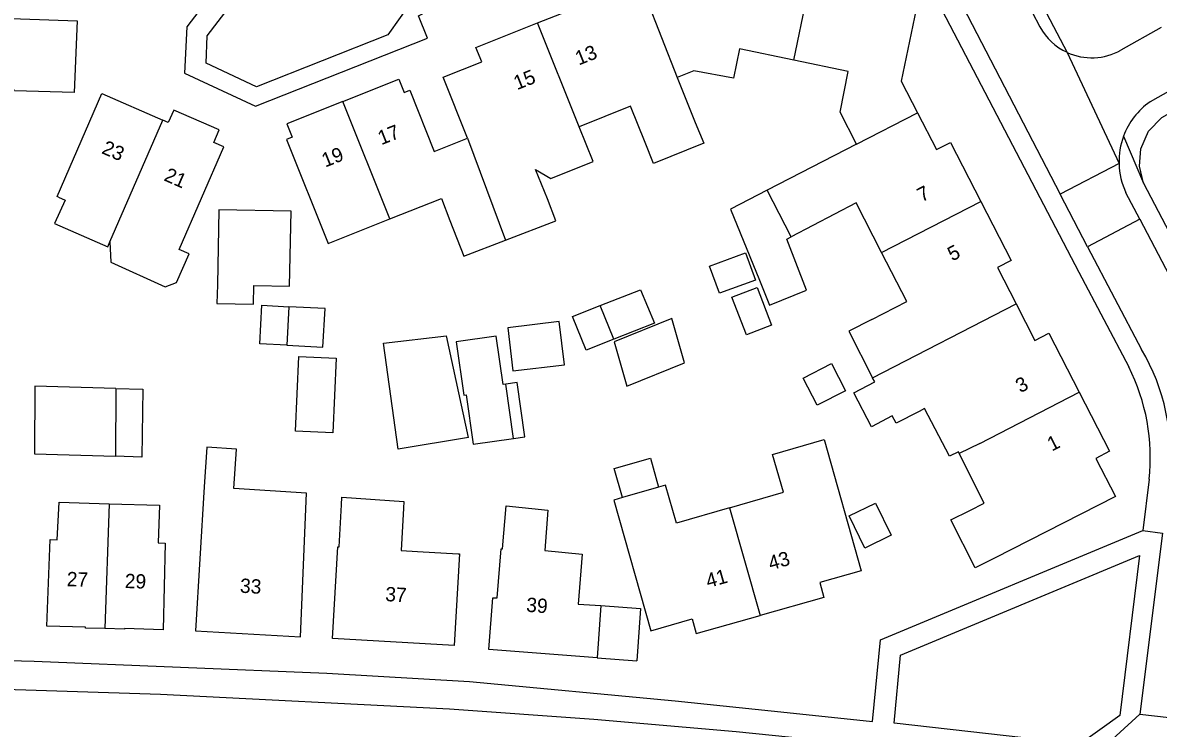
# Model space of a CAD drawing. Extents: x 194485 to 197793, y 468269 to 470822.
# Drawn here: x 195092.1 to 195187.3, y 470211.6 to 470270.8 of the extents above; entities that cross this region are included whole.
import ezdxf

# ---------------------------------------------------------------- set-up
doc = ezdxf.new("R2010")
doc.units = 0
for name, color, linetype in [('BGT grensvlak gebouwinstallatie plus 1', 7, 'Continuous'), ('BGT grensvlak overig bouwwerk uitbreiding populatie', 7, 'Continuous'), ('BGT grensvlak pand op maaiveld', 7, 'Continuous'), ('BGT grensvlak pand op maaiveld LR', 7, 'Continuous'), ('BGT grensvlak wegdeel', 7, 'Continuous'), ('BGT tekst huisnummerreeks', 7, 'Continuous')]:
    doc.layers.add(name, color=color, linetype=linetype)

msp = doc.modelspace()

# ---------------------------------------------------------------- linework, layer by layer
at = {"layer": 'BGT grensvlak gebouwinstallatie plus 1'}
for p, q in [((195154.51, 470256.704), (195151.434, 470255.12)), ((195151.434, 470255.12), (195153.855, 470249.162)), ((195156.152, 470252.615), (195156.515, 470252.803)), ((195157.792, 470248.326), (195156.152, 470252.615)), ((195153.855, 470249.162), (195154.704, 470247.072)), ((195154.704, 470247.072), (195157.792, 470248.326)), ((195117.456, 470246.783), (195114.433, 470246.946)), ((195117.282, 470243.545), (195117.456, 470246.783)), ((195114.259, 470243.707), (195117.282, 470243.545)), ((195141.683, 470233.384), (195144.719, 470234.234)), ((195144.719, 470234.234), (195145.4, 470231.804)), ((195142.37, 470230.933), (195141.683, 470233.384)), ((195140.568, 470221.876), (195143.88, 470221.651)), ((195143.88, 470221.651), (195143.575, 470217.238)), ((195140.266, 470217.496), (195143.575, 470217.238))]:
    msp.add_line(p, q, dxfattribs=at)
for points in [[(195141.652, 470244.219), (195139.344, 470243.289), (195138.201, 470246.125), (195140.509, 470247.055)], [(195133.204, 470241.559), (195137.518, 470242.078), (195137.082, 470245.703), (195132.768, 470245.184), (195133.204, 470241.559)], [(195146.524, 470245.946), (195141.674, 470244.006), (195142.735, 470240.288), (195147.585, 470242.229), (195146.524, 470245.946)], [(195133.258, 470235.894), (195134.192, 470236.026), (195133.548, 470240.577), (195132.614, 470240.444)]]:
    msp.add_lwpolyline(points, dxfattribs=at)
at = {"layer": 'BGT grensvlak overig bouwwerk uitbreiding populatie'}
for p, q in [((195149.68, 470250.358), (195152.685, 470251.45)), ((195152.685, 470251.45), (195153.517, 470249.161)), ((195150.512, 470248.069), (195149.68, 470250.358)), ((195153.517, 470249.161), (195150.512, 470248.069)), ((195151.553, 470247.75), (195153.667, 470248.557)), ((195153.667, 470248.557), (195154.873, 470245.398)), ((195152.76, 470244.591), (195151.553, 470247.75)), ((195111.992, 470243.829), (195112.166, 470247.067)), ((195112.166, 470247.067), (195114.433, 470246.946)), ((195114.433, 470246.946), (195114.259, 470243.707)), ((195154.873, 470245.398), (195152.76, 470244.591)), ((195114.259, 470243.707), (195111.992, 470243.829)), ((195157.526, 470240.964), (195159.9, 470242.172)), ((195159.9, 470242.172), (195161.06, 470239.893)), ((195158.686, 470238.684), (195157.526, 470240.964)), ((195161.06, 470239.893), (195158.686, 470238.684))]:
    msp.add_line(p, q, dxfattribs=at)
at = {"layer": 'BGT grensvlak pand op maaiveld'}
for p, q in [((195146.957, 470266.177), (195148.48, 470262.391)), ((195104.32, 470262.388), (195103.88, 470262.58)), ((195104.776, 470263.433), (195104.32, 470262.388)), ((195108.59, 470261.767), (195104.776, 470263.433)), ((195108.133, 470260.723), (195108.59, 470261.767)), ((195162, 470260.562), (195154.51, 470256.704)), ((195136.09, 470256.004), (195135.104, 470258.458)), ((195156.515, 470252.803), (195154.51, 470256.704)), ((195161.964, 470255.643), (195156.515, 470252.803)), ((195164.098, 470251.491), (195161.964, 470255.643)), ((195140.509, 470247.055), (195143.889, 470248.369)), ((195141.652, 470244.219), (195140.509, 470247.055)), ((195129.49, 470235.969), (195127.624, 470244.509)), ((195163.519, 470240.646), (195163.345, 470240.985)), ((195133.258, 470235.894), (195132.614, 470240.444)), ((195167.702, 470238.402), (195167.236, 470238.162)), ((195172.679, 470230.467), (195170.607, 470234.623)), ((195145.4, 470231.804), (195142.37, 470230.933)), ((195171.501, 470229.862), (195172.679, 470230.467)), ((195124.029, 470230.042), (195123.84, 470226.509)), ((195123.84, 470226.509), (195125.201, 470226.429)), ((195125.201, 470226.429), (195128.625, 470226.228)), ((195140.568, 470221.876), (195140.266, 470217.496))]:
    msp.add_line(p, q, dxfattribs=at)
for points in [[(195158.616, 470276.679), (195164.068, 470275.544), (195163.462, 470272.606), (195166.993, 470271.905), (195165.741, 470265.864), (195167.115, 470263.198)], [(195135.26, 470270.736), (195140.419, 470272.798), (195140.901, 470271.591), (195144.326, 470272.951)], [(195096.449, 470264.899), (195091.441, 470265.047), (195087.958, 470271.234), (195096.684, 470270.927), (195096.449, 470264.899)], [(195129.392, 470261.087), (195127.348, 470266.193), (195130.585, 470267.467), (195130.101, 470268.673), (195135.26, 470270.736)], [(195156.73, 470267.621), (195152.188, 470268.566), (195151.678, 470266.118), (195148.355, 470266.72), (195146.957, 470266.177)], [(195162, 470260.562), (195160.622, 470263.245), (195161.302, 470266.669), (195156.73, 470267.621)], [(195118.954, 470264.149), (195123.655, 470266.021), (195124.098, 470264.906), (195124.563, 470265.091)], [(195095.136, 470256.119), (195095.013, 470256.173), (195098.769, 470264.811), (195103.88, 470262.58)], [(195124.563, 470265.091), (195126.596, 470259.972), (195129.392, 470261.087)], [(195118.954, 470264.149), (195114.253, 470262.277), (195114.697, 470261.162), (195114.232, 470260.977)], [(195144.295, 470260.708), (195143.067, 470263.76), (195138.744, 470262.02)], [(195167.115, 470263.198), (195168.701, 470260.119), (195169.856, 470260.714), (195172.403, 470255.77)], [(195135.104, 470258.458), (195136.392, 470257.69), (195139.914, 470259.108), (195138.744, 470262.02)], [(195148.48, 470262.391), (195149.2, 470260.65), (195144.971, 470258.952), (195144.295, 470260.708)], [(195105.227, 470251.75), (195108.991, 470260.348), (195108.133, 470260.723)], [(195114.232, 470260.977), (195117.71, 470252.244), (195122.875, 470254.303)], [(195095.136, 470256.119), (195095.675, 470255.885), (195094.793, 470253.909)], [(195122.875, 470254.303), (195127.213, 470256.032), (195127.929, 470254.174)], [(195132.576, 470252.524), (195136.79, 470254.158), (195136.09, 470256.004)], [(195111.503, 470248.725), (195114.49, 470248.671), (195114.625, 470254.96), (195108.566, 470255.08), (195108.448, 470248.781)], [(195172.403, 470255.77), (195174.95, 470250.827), (195173.794, 470250.232), (195175.368, 470247.177)], [(195127.929, 470254.174), (195129.086, 470251.171), (195132.576, 470252.524)], [(195094.793, 470253.909), (195099.249, 470251.973), (195099.427, 470252.38)], [(195099.427, 470252.38), (195099.504, 470250.689), (195104.053, 470248.624), (195105.022, 470248.972), (195106.066, 470251.385), (195105.227, 470251.75)], [(195163.273, 470245.876), (195166.208, 470247.384), (195164.098, 470251.491)], [(195108.448, 470248.781), (195108.402, 470247.211), (195111.466, 470247.164), (195111.503, 470248.725)], [(195143.889, 470248.369), (195145.055, 470245.555), (195141.652, 470244.219)], [(195175.368, 470247.177), (195176.941, 470244.122), (195178.097, 470244.717), (195180.645, 470239.77)], [(195163.273, 470245.876), (195161.342, 470244.884), (195163.345, 470240.985)], [(195129.49, 470235.969), (195123.597, 470234.996), (195122.366, 470243.875), (195127.624, 470244.509)], [(195132.614, 470240.444), (195132.373, 470240.41), (195131.799, 470244.47), (195128.453, 470243.996), (195129.087, 470239.519), (195129.285, 470239.547), (195129.87, 470235.414), (195133.258, 470235.894)], [(195118.402, 470242.634), (195118.107, 470236.365), (195114.972, 470236.513), (195115.268, 470242.782), (195118.402, 470242.634)], [(195164.989, 470237.785), (195163.256, 470236.877), (195161.764, 470239.726), (195163.519, 470240.646)], [(195099.922, 470240.095), (195093.132, 470240.295), (195093.121, 470234.619), (195099.904, 470234.404)], [(195099.922, 470240.095), (195102.201, 470240.028), (195102.113, 470234.334), (195099.904, 470234.404)], [(195180.645, 470239.77), (195183.193, 470234.824), (195182.039, 470234.23), (195183.688, 470231.028), (195173.562, 470225.85)], [(195167.236, 470238.162), (195165.305, 470237.169), (195164.989, 470237.785)], [(195170.607, 470234.623), (195170.534, 470234.771), (195169.776, 470234.413), (195167.702, 470238.402)], [(195109.824, 470231.687), (195110.047, 470235.001), (195107.546, 470235.159), (195107.322, 470231.845)], [(195151.347, 470230.082), (195155.871, 470231.384), (195154.959, 470234.555), (195159.284, 470235.799), (195162.37, 470224.802), (195158.905, 470223.816), (195159.26, 470222.566), (195153.912, 470221.047)], [(195107.322, 470231.845), (195106.607, 470219.775), (195115.4, 470219.266), (195115.899, 470231.305), (195109.824, 470231.687)], [(195151.347, 470230.082), (195146.905, 470228.804), (195145.993, 470231.975), (195145.4, 470231.804)], [(195099.013, 470219.948), (195097.395, 470220), (195097.397, 470220.06), (195094.149, 470220.165), (195094.414, 470227.424), (195095.018, 470227.405), (195095.176, 470230.557), (195099.384, 470230.425)], [(195099.384, 470230.425), (195103.591, 470230.292), (195103.47, 470227.142), (195104.065, 470227.124), (195103.883, 470219.85), (195100.645, 470219.955), (195100.643, 470219.895), (195099.013, 470219.948)], [(195128.625, 470226.228), (195128.728, 470226.222), (195128.283, 470218.525), (195118.075, 470219.113), (195118.538, 470226.82), (195118.642, 470226.814), (195118.848, 470230.329)], [(195118.848, 470230.329), (195118.879, 470230.986), (195124.069, 470230.623), (195124.029, 470230.042)], [(195140.266, 470217.496), (195131.187, 470218.203), (195131.528, 470222.544), (195131.872, 470222.546), (195132.228, 470226.633), (195132.33, 470226.634), (195132.637, 470230.25), (195136.132, 470229.89)], [(195142.37, 470230.933), (195141.668, 470230.731), (195144.758, 470219.779), (195148.21, 470220.78), (195148.565, 470219.529), (195153.912, 470221.047)], [(195161.375, 470229.404), (195163.578, 470230.476), (195164.9, 470227.797), (195162.682, 470226.711), (195161.375, 470229.404)], [(195136.132, 470229.89), (195135.874, 470226.504), (195139.011, 470226.193), (195138.681, 470222.004), (195140.568, 470221.876)], [(195173.562, 470225.85), (195171.945, 470225.059), (195169.885, 470229.078), (195171.501, 470229.862)]]:
    msp.add_lwpolyline(points, dxfattribs=at)
at = {"layer": 'BGT grensvlak pand op maaiveld LR'}
for p, q in [((195156.73, 470267.621), (195158.616, 470276.679)), ((195144.326, 470272.951), (195146.957, 470266.177)), ((195138.744, 470262.02), (195135.26, 470270.736)), ((195122.875, 470254.303), (195118.954, 470264.149)), ((195099.427, 470252.38), (195103.88, 470262.58)), ((195162, 470260.562), (195167.115, 470263.198)), ((195129.392, 470261.087), (195132.576, 470252.524)), ((195164.098, 470251.491), (195172.403, 470255.77)), ((195163.345, 470240.985), (195175.368, 470247.177)), ((195099.922, 470240.095), (195099.904, 470234.404)), ((195172.322, 470235.484), (195180.645, 470239.77)), ((195172.322, 470235.484), (195170.607, 470234.623)), ((195099.384, 470230.425), (195099.013, 470219.948)), ((195151.347, 470230.082), (195153.912, 470221.047))]:
    msp.add_line(p, q, dxfattribs=at)
at = {"layer": 'BGT grensvlak wegdeel'}
for p, q in [((195257.786, 470304.19), (195186.59, 470264.129)), ((195172.727, 470279.307), (195177.359, 470270.405)), ((195168.6, 470276.541), (195179.066, 470256.372)), ((195177.916, 470271.56), (195179.631, 470268.275)), ((195187.51, 470270.349), (195184.148, 470268.464)), ((195179.631, 470268.275), (195183.988, 470258.945)), ((195184.365, 470261.241), (195186.05, 470257.296)), ((195183.988, 470258.945), (195179.066, 470256.372)), ((195186.05, 470257.296), (195197.6, 470235.068)), ((195181.357, 470251.976), (195179.066, 470256.372)), ((195185.726, 470254.272), (195184.572, 470256.5)), ((195185.726, 470254.272), (195181.357, 470251.976)), ((195185.726, 470254.272), (195190.121, 470245.856)), ((195181.357, 470251.976), (195185.871, 470243.353)), ((195186.506, 470232.47), (195185.977, 470228.165)), ((195187.621, 470227.967), (195185.719, 470212.767)), ((195185.977, 470228.165), (195187.621, 470227.967)), ((195180.735, 470208.234), (195185.719, 470212.767)), ((195185.719, 470212.767), (195190.739, 470212.196))]:
    msp.add_line(p, q, dxfattribs=at)
for points in [[(195126.923, 470309.305), (195136.889, 470293.172), (195112.481, 470279.057), (195105.88, 470270.408), (195105.675, 470266.523), (195111.619, 470263.774), (195126.042, 470269.456), (195125.289, 470271.336), (195144.366, 470281.295), (195145.521, 470281.675), (195146.732, 470281.559), (195164.933, 470277.295)], [(195186.05, 470257.296), (195185.7, 470258.725), (195185.821, 470260.191), (195186.471, 470261.654), (195187.584, 470262.804), (195257.348, 470302.049)], [(195141.437, 470281.408), (195124.798, 470272.664), (195122.733, 470269.755), (195111.703, 470265.392), (195107.488, 470267.362), (195107.591, 470269.665), (195114.41, 470278.564), (195116.561, 470279.825)], [(195167.175, 470275.617), (195180.611, 470249.844), (195184.798, 470241.894)], [(195023.43, 470219.099), (195038.961, 470218.596), (195055.019, 470218.224), (195093.086, 470217.222), (195117.607, 470216.217), (195129.567, 470215.513), (195146.802, 470213.9), (195156.185, 470212.928), (195163.328, 470212.171), (195163.994, 470219.016), (195185.977, 470228.165)], [(195165.152, 470212.015), (195165.684, 470217.728), (195185.712, 470226.088), (195184.061, 470212.659), (195180.702, 470210.27), (195165.152, 470212.015)], [(195056.711, 470215.952), (195103.659, 470214.441), (195127.894, 470213.219), (195139.968, 470212.366), (195151.904, 470211.321), (195163.967, 470210.08), (195180.735, 470208.234)]]:
    msp.add_lwpolyline(points, dxfattribs=at)
for centre, radius, start, end in [((195181.682, 470272.74), 4.913, 208.36998, 245.32524), ((195181.705, 470272.772), 4.953, 245.23922, 299.55272), ((195190.119, 470259.109), 6.136, 125.10585, 159.67073), ((195190.086, 470259.123), 6.1, 159.68154, 181.66911), ((195190.099, 470259.112), 6.113, 181.56836, 205.29899), ((195170.956, 470234.495), 17.347, 353.33386, 30.70733), ((195169.838, 470234.316), 16.77, 353.68038, 26.8651)]:
    msp.add_arc(centre, radius, start, end, dxfattribs=at)

# ---------------------------------------------------------------- texts
at = {"layer": 'BGT tekst huisnummerreeks'}
for s, rotation, p in [('13', 21.8, (195138.717, 470267.164)), ('15', 21.8, (195133.554, 470265.099)), ('17', 21.7, (195122.175, 470260.481)), ('23', 336.4, (195098.665, 470259.838)), ('19', 21.7, (195117.473, 470258.609)), ('21', 336.4, (195103.882, 470257.56)), ('7', 27.3, (195167.469, 470255.681)), ('5', 27.3, (195170.012, 470250.734)), ('3', 27.3, (195175.71, 470239.683)), ('1', 27.3, (195178.361, 470234.789)), ('43', 15.9, (195154.798, 470224.832)), ('27', 358.1, (195095.801, 470223.514)), ('29', 358.1, (195100.667, 470223.357)), ('41', 15.8, (195149.561, 470223.347)), ('33', 356.7, (195110.308, 470222.966)), ('37', 356.7, (195122.482, 470222.264)), ('39', 355.5, (195134.286, 470221.373))]:
    msp.add_text(s, height=1.2, rotation=rotation, dxfattribs=at).set_placement(p)

doc.saveas('drawing.dxf')
